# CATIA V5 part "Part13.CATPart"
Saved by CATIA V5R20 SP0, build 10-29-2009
Part number: FV161320-4
Revision: ANY
Definition: UNKNOWN
Nomenclature: FV161320-4
Source: Unknown
Bounding box of the stored display mesh (mm): x -6.24 to 6.24, y 0 to 1.8, z -6.4 to 6.4
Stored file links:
  C:\Users\Utente\Desktop\IO LAVORO\3D X SITO CF\CUMSA\3D files FV\FV 201720\Part13.CATPart
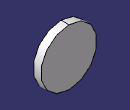
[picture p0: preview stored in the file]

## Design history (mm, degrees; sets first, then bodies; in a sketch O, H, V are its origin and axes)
Body1 "Saliente-Extruir1" (main body)
  Solid1: solid without history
